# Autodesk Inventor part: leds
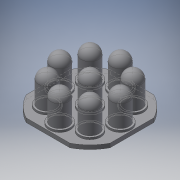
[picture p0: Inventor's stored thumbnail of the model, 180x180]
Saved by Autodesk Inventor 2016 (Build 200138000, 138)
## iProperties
Created: 2015-05
Part Number: leds
Material: Generic
Document SubType Name: Modeling
Designer: Brent
Density: 1 g/cm^3
Appearance: Default
Author: Brent
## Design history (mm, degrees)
sketch "Sketch1"
  geometry: L1 (-5.495, 10.541)-(5.495, 10.541); L2 (10.541, 5.495)-(10.541, -5.495); L3 (5.495, -10.541)-(-5.495, -10.541); L4 (-10.541, -5.495)-(-10.541, 5.495); L5 (-10.541, 10.541)-(10.541, -10.541); L6 (10.541, 10.541)-(-10.541, -10.541); A1 r 11.887 centre (0, 0) between (-10.541, -5.495) and (-5.495, -10.541); A2 r 11.887 centre (0, 0) between (5.495, -10.541) and (10.541, -5.495); A3 r 11.887 centre (0, 0) between (10.541, 5.495) and (5.495, 10.541); A4 r 11.887 centre (0, 0) between (-5.495, 10.541) and (-10.541, 5.495); 1 further point
  constraints: 12 end point, 8 point on circle, 4 centre point, 2 midpoint, 2 parallel, 1 coincident, 1 horizontal, 1 perpendicular
  dimensions: "d1" = 21.082 distance of L5.end L6.end; "d2" = 21.082 distance of L6.start L5.end
extrude "Extrusion1" new body sketch "Sketch1" distance "d3" = 1.016; taper "d4" = 0 deg
sketch "Sketch2" dims "d5" = 15.24
  geometry: C1 r 2.667 at (0, 0); C2 r 2.667 at (-7.62, 0); C3 r 2.667 at (-5.388, -5.388); C4 r 2.667 at (0, -7.62); C5 r 2.667 at (5.388, -5.388); C6 r 2.667 at (7.62, 0); C7 r 2.667 at (5.388, 5.388); C8 r 2.667 at (0, 7.62); C9 r 2.667 at (-5.388, 5.388); 2 further points
  constraints: 9 centre point, 2 coincident, 1 horizontal alignment, 19 other
  dimensions: "d6" = 5.334 diameter of C1; "d7" = 5.334 diameter of C2; "d10" = 360 deg dimension on point (0, 0) C2.centre (derived)
extrude "Extrusion2" join sketch "Sketch2" distance "d12" = 0.508; taper "d13" = 0 deg
sketch "Sketch3"
  geometry: C1 r 2.667 at (-5.388, 5.388) reference; C2 r 2.667 at (0, 0) reference; C3 r 2.667 at (5.388, 5.388) reference; C4 r 2.667 at (0, 7.62) reference; C5 r 2.667 at (7.62, 0) reference; C6 r 2.667 at (5.388, -5.388) reference; C7 r 2.667 at (0, -7.62) reference; C8 r 2.667 at (-5.388, -5.388) reference; C9 r 2.667 at (-7.62, 0) reference; C10 r 2.21 at (0, 0); C11 r 2.21 at (-5.388, 5.388); C12 r 2.21 at (0, 7.62); C13 r 2.21 at (5.388, 5.388); C14 r 2.21 at (7.62, 0); C15 r 2.21 at (5.388, -5.388); C16 r 2.21 at (0, -7.62); C17 r 2.21 at (-5.388, -5.388); C18 r 2.21 at (-7.62, 0); 1 further point
  constraints: 9 centre point, 9 coincident
  dimensions: "d14" = 4.4196 diameter of C10; "d15" = 4.4196 diameter of C11; "d16" = 4.4196 diameter of C12; "d17" = 4.4196 diameter of C13; "d18" = 4.4196 diameter of C14; "d19" = 4.4196 diameter of C15; "d20" = 4.4196 diameter of C16; "d21" = 4.4196 diameter of C17; "d22" = 4.4196 diameter of C18
extrude "Extrusion3" join sketch "Sketch3" distance "d23" = 7.62; taper "d24" = 0 deg
fillet "Fillet1" dims "d25" = 2.2098
body "Solid1"
node "Projected Loop1"
node "Projected Loop2"
node "Projected Loop3"
node "Projected Loop4"
node "Projected Loop5"
node "Projected Loop6"
node "Projected Loop7"
node "Projected Loop8"
node "Projected Loop9"
other parameters: "d0" = 23.7744
